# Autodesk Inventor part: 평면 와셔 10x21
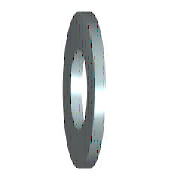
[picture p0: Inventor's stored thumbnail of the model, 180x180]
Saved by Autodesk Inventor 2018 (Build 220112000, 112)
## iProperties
IsCustomPart: 1
Created: 2012-02
Part Number: 평면 와셔 10x21
Material: 강철, 연강
Description: 평면 와셔
Document SubType Name: Modeling
Standard: KS B 1326
Designer: mduedu
Standards Organization: KS
Language: ko-KR
Size Designation: 10x21
Categories: <MemberInstance><Categories><Category DisplayName="조임쇠" InternalName="e4da775c-781d-43d5-af7c-5136215cf5a6" Mnemonic="FSTN"><Category DisplayName="와셔" InternalN
Density: 1 g/cm^3
Appearance: 노란색
Author: mduedu
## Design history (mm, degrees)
sketch "스케치"
  geometry: C1 r 10.5 at (0, 0); C2 r 5.25 at (0, 0); 1 further point
  constraints: 2 centre point, 2 coincident
  dimensions: "d0" = 10.5 diameter of C2 (= SD1); "d1" = 21 diameter of C1 (= SD2)
extrude "본체" new body sketch "스케치" distance "d2" = 2 (= SD); taper "d3" = 0 deg
workaxis "Work Axis1"
workplane "Work Plane1"
body "Solid1"
other parameters: "SD1" = 10.5 [user parameter; used in 1 equation term], "SD2" = 21 [user parameter; used in 1 equation term], "SD" = 2 [user parameter; used in 1 equation term], "d4" = 0, "d5" = 0, "d6" = 0, "d7" = 0
